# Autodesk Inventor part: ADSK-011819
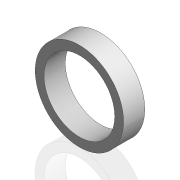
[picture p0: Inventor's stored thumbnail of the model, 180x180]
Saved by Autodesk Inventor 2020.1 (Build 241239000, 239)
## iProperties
Created: 2000-02
Part Number: ADSK-011819
Material: Pearson UHMW
Document SubType Name: Modeling
Designer: cmcgourin
Density: 0.94 g/cm^3
Appearance: UHMW White
Mass: 0.99667 g
Surface Area: 12.0166 cm^2
Volume: 1.06029 cm^3
Control State: 0
Master: False
Checked Out: False
Shininess: 0.0
Length Units: 11269
Angle Units: 11279
Time Units: 11290
Mass Units: 11283
Length Display Precision: 3
Angle Display Precision: 2
Compacted: True
Dimensions: 25x25x6 mm
Mass: 0,001 kg
DocNumber: ADSK-011819.ipt
Folder: 01 - Themengebiete\Simplification\01 - Packaging machine\
VDS_Category: 3D Komponenten
Density: 0.0
Volumn: 0.0
Area: 0.0
PropertySet Name: Model Information
Author: cmcgourin
Revision Number: -
Title: buffer
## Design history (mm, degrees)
node "Solide1"
  node "Extrusion1" dims "d4" = 6, "d5" = 0
sketch "Sketch1"
  geometry: C1 r 12.5 at (46.038, 0); C2 r 10 at (46.038, 0); 2 further points
  constraints: 2 centre point, 2 coincident
  dimensions: "d1" = 25 diameter of C1; "d3" = 20 diameter of C2
node "Corps solides"
node "Corps surfaciques"
